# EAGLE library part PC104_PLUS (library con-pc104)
PC/104-Plus 16 bit
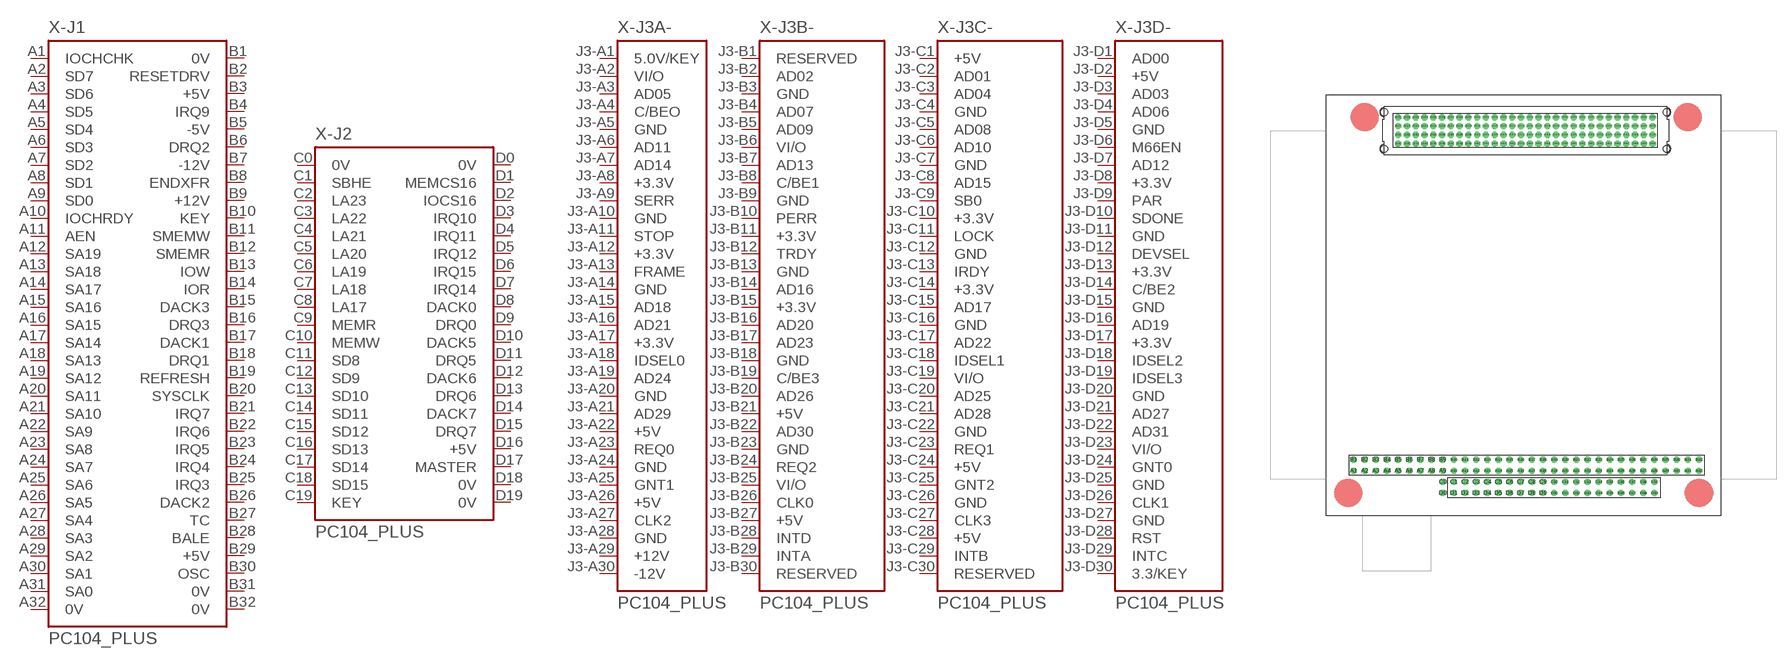
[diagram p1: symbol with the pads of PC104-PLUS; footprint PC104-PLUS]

Designator prefix X; gates -J1=PC104-J1 -J2=PC104-J2 -J3A-=PC104J3A -J3B-=PC104J3B -J3C-=PC104J3C -J3D-=PC104J3D

## PC104_PLUS  [PC104-PLUS]
A1  -J1:IOCHCHK  pas
A2  -J1:SD7  pas
A3  -J1:SD6  pas
A4  -J1:SD5  pas
A5  -J1:SD4  pas
A6  -J1:SD3  pas
A7  -J1:SD2  pas
A8  -J1:SD1  pas
A9  -J1:SD0  pas
A10  -J1:IOCHRDY  pas
A11  -J1:AEN  pas
A12  -J1:SA19  pas
A13  -J1:SA18  pas
A14  -J1:SA17  pas
A15  -J1:SA16  pas
A16  -J1:SA15  pas
A17  -J1:SA14  pas
A18  -J1:SA13  pas
A19  -J1:SA12  pas
A20  -J1:SA11  pas
A21  -J1:SA10  pas
A22  -J1:SA9  pas
A23  -J1:SA8  pas
A24  -J1:SA7  pas
A25  -J1:SA6  pas
A26  -J1:SA5  pas
A27  -J1:SA4  pas
A28  -J1:SA3  pas
A29  -J1:SA2  pas
A30  -J1:SA1  pas
A31  -J1:SA0  pas
A32  -J1:0V  pas
B1  -J1:0V  pas
B2  -J1:RESETDRV  pas
B3  -J1:+5V  pas
B4  -J1:IRQ9  pas
B5  -J1:-5V  pas
B6  -J1:DRQ2  pas
B7  -J1:-12V  pas
B8  -J1:ENDXFR  pas
B9  -J1:+12V  pas
B10  -J1:KEY  pas
B11  -J1:SMEMW  pas
B12  -J1:SMEMR  pas
B13  -J1:IOW  pas
B14  -J1:IOR  pas
B15  -J1:DACK3  pas
B16  -J1:DRQ3  pas
B17  -J1:DACK1  pas
B18  -J1:DRQ1  pas
B19  -J1:REFRESH  pas
B20  -J1:SYSCLK  pas
B21  -J1:IRQ7  pas
B22  -J1:IRQ6  pas
B23  -J1:IRQ5  pas
B24  -J1:IRQ4  pas
B25  -J1:IRQ3  pas
B26  -J1:DACK2  pas
B27  -J1:TC  pas
B28  -J1:BALE  pas
B29  -J1:+5V  pas
B30  -J1:OSC  pas
B31  -J1:0V  pas
B32  -J1:0V  pas
C0  -J2:0V  pas
C1  -J2:SBHE  pas
C2  -J2:LA23  pas
C3  -J2:LA22  pas
C4  -J2:LA21  pas
C5  -J2:LA20  pas
C6  -J2:LA19  pas
C7  -J2:LA18  pas
C8  -J2:LA17  pas
C9  -J2:MEMR  pas
C10  -J2:MEMW  pas
C11  -J2:SD8  pas
C12  -J2:SD9  pas
C13  -J2:SD10  pas
C14  -J2:SD11  pas
C15  -J2:SD12  pas
C16  -J2:SD13  pas
C17  -J2:SD14  pas
C18  -J2:SD15  pas
C19  -J2:KEY  pas
D0  -J2:0V  pas
D1  -J2:MEMCS16  pas
D2  -J2:IOCS16  pas
D3  -J2:IRQ10  pas
D4  -J2:IRQ11  pas
D5  -J2:IRQ12  pas
D6  -J2:IRQ15  pas
D7  -J2:IRQ14  pas
D8  -J2:DACK0  pas
D9  -J2:DRQ0  pas
D10  -J2:DACK5  pas
D11  -J2:DRQ5  pas
D12  -J2:DACK6  pas
D13  -J2:DRQ6  pas
D14  -J2:DACK7  pas
D15  -J2:DRQ7  pas
D16  -J2:+5V  pas
D17  -J2:MASTER  pas
D18  -J2:0V  pas
D19  -J2:0V  pas
J3-A1  -J3A-:5.0V/KEY  pas
J3-A2  -J3A-:VI/O  pas
J3-A3  -J3A-:AD05  pas
J3-A4  -J3A-:C/BEO  pas
J3-A5  -J3A-:GND  pas
J3-A6  -J3A-:AD11  pas
J3-A7  -J3A-:AD14  pas
J3-A8  -J3A-:+3.3V  pas
J3-A9  -J3A-:SERR  pas
J3-A10  -J3A-:GND  pas
J3-A11  -J3A-:STOP  pas
J3-A12  -J3A-:+3.3V  pas
J3-A13  -J3A-:FRAME  pas
J3-A14  -J3A-:GND  pas
J3-A15  -J3A-:AD18  pas
J3-A16  -J3A-:AD21  pas
J3-A17  -J3A-:+3.3V  pas
J3-A18  -J3A-:IDSEL0  pas
J3-A19  -J3A-:AD24  pas
J3-A20  -J3A-:GND  pas
J3-A21  -J3A-:AD29  pas
J3-A22  -J3A-:+5V  pas
J3-A23  -J3A-:REQ0  pas
J3-A24  -J3A-:GND  pas
J3-A25  -J3A-:GNT1  pas
J3-A26  -J3A-:+5V  pas
J3-A27  -J3A-:CLK2  pas
J3-A28  -J3A-:GND  pas
J3-A29  -J3A-:+12V  pas
J3-A30  -J3A-:-12V  pas
J3-B1  -J3B-:RESERVED  pas
J3-B2  -J3B-:AD02  pas
J3-B3  -J3B-:GND  pas
J3-B4  -J3B-:AD07  pas
J3-B5  -J3B-:AD09  pas
J3-B6  -J3B-:VI/O  pas
J3-B7  -J3B-:AD13  pas
J3-B8  -J3B-:C/BE1  pas
J3-B9  -J3B-:GND  pas
J3-B10  -J3B-:PERR  pas
J3-B11  -J3B-:+3.3V  pas
J3-B12  -J3B-:TRDY  pas
J3-B13  -J3B-:GND  pas
J3-B14  -J3B-:AD16  pas
J3-B15  -J3B-:+3.3V  pas
J3-B16  -J3B-:AD20  pas
J3-B17  -J3B-:AD23  pas
J3-B18  -J3B-:GND  pas
J3-B19  -J3B-:C/BE3  pas
J3-B20  -J3B-:AD26  pas
J3-B21  -J3B-:+5V  pas
J3-B22  -J3B-:AD30  pas
J3-B23  -J3B-:GND  pas
J3-B24  -J3B-:REQ2  pas
J3-B25  -J3B-:VI/O  pas
J3-B26  -J3B-:CLK0  pas
J3-B27  -J3B-:+5V  pas
J3-B28  -J3B-:INTD  pas
J3-B29  -J3B-:INTA  pas
J3-B30  -J3B-:RESERVED  pas
J3-C1  -J3C-:+5V  pas
J3-C2  -J3C-:AD01  pas
J3-C3  -J3C-:AD04  pas
J3-C4  -J3C-:GND  pas
J3-C5  -J3C-:AD08  pas
J3-C6  -J3C-:AD10  pas
J3-C7  -J3C-:GND  pas
J3-C8  -J3C-:AD15  pas
J3-C9  -J3C-:SB0  pas
J3-C10  -J3C-:+3.3V  pas
J3-C11  -J3C-:LOCK  pas
J3-C12  -J3C-:GND  pas
J3-C13  -J3C-:IRDY  pas
J3-C14  -J3C-:+3.3V  pas
J3-C15  -J3C-:AD17  pas
J3-C16  -J3C-:GND  pas
J3-C17  -J3C-:AD22  pas
J3-C18  -J3C-:IDSEL1  pas
J3-C19  -J3C-:VI/O  pas
J3-C20  -J3C-:AD25  pas
J3-C21  -J3C-:AD28  pas
J3-C22  -J3C-:GND  pas
J3-C23  -J3C-:REQ1  pas
J3-C24  -J3C-:+5V  pas
J3-C25  -J3C-:GNT2  pas
J3-C26  -J3C-:GND  pas
J3-C27  -J3C-:CLK3  pas
J3-C28  -J3C-:+5V  pas
J3-C29  -J3C-:INTB  pas
J3-C30  -J3C-:RESERVED  pas
J3-D1  -J3D-:AD00  pas
J3-D2  -J3D-:+5V  pas
J3-D3  -J3D-:AD03  pas
J3-D4  -J3D-:AD06  pas
J3-D5  -J3D-:GND  pas
J3-D6  -J3D-:M66EN  pas
J3-D7  -J3D-:AD12  pas
J3-D8  -J3D-:+3.3V  pas
J3-D9  -J3D-:PAR  pas
J3-D10  -J3D-:SDONE  pas
J3-D11  -J3D-:GND  pas
J3-D12  -J3D-:DEVSEL  pas
J3-D13  -J3D-:+3.3V  pas
J3-D14  -J3D-:C/BE2  pas
J3-D15  -J3D-:GND  pas
J3-D16  -J3D-:AD19  pas
J3-D17  -J3D-:+3.3V  pas
J3-D18  -J3D-:IDSEL2  pas
J3-D19  -J3D-:IDSEL3  pas
J3-D20  -J3D-:GND  pas
J3-D21  -J3D-:AD27  pas
J3-D22  -J3D-:AD31  pas
J3-D23  -J3D-:VI/O  pas
J3-D24  -J3D-:GNT0  pas
J3-D25  -J3D-:GND  pas
J3-D26  -J3D-:CLK1  pas
J3-D27  -J3D-:GND  pas
J3-D28  -J3D-:RST  pas
J3-D29  -J3D-:INTC  pas
J3-D30  -J3D-:3.3/KEY  pas

## Footprint PC104-PLUS (pad centres in mm)
PC/104-Plus 16 bit
drill 0.9 octagon: A1 6.35,10.16; A2 8.89,10.16; A3 11.43,10.16; A4 13.97,10.16; A5 16.51,10.16; A6 19.05,10.16; A7 21.59,10.16; A8 24.13,10.16; A9 26.67,10.16; A10 29.21,10.16; A11 31.75,10.16; A12 34.29,10.16; A13 36.83,10.16; A14 39.37,10.16; A15 41.91,10.16; A16 44.45,10.16; A17 46.99,10.16; A18 49.53,10.16; A19 52.07,10.16; A20 54.61,10.16; A21 57.15,10.16; A22 59.69,10.16; A23 62.23,10.16; A24 64.77,10.16; A25 67.31,10.16; A26 69.85,10.16; A27 72.39,10.16; A28 74.93,10.16; A29 77.47,10.16; A30 80.01,10.16; A31 82.55,10.16; A32 85.09,10.16; B1 6.35,12.7; B2 8.89,12.7; B3 11.43,12.7; B4 13.97,12.7; B5 16.51,12.7; B6 19.05,12.7; B7 21.59,12.7; B8 24.13,12.7; B9 26.67,12.7; B10 29.21,12.7; B11 31.75,12.7; B12 34.29,12.7; B13 36.83,12.7; B14 39.37,12.7; B15 41.91,12.7; B16 44.45,12.7; B17 46.99,12.7; B18 49.53,12.7; B19 52.07,12.7; B20 54.61,12.7; B21 57.15,12.7; B22 59.69,12.7; B23 62.23,12.7; B24 64.77,12.7; B25 67.31,12.7; B26 69.85,12.7; B27 72.39,12.7; B28 74.93,12.7; B29 77.47,12.7; B30 80.01,12.7; B31 82.55,12.7; B32 85.09,12.7; C0 26.67,7.62; C1 29.21,7.62; C2 31.75,7.62; C3 34.29,7.62; C4 36.83,7.62; C5 39.37,7.62; C6 41.91,7.62; C7 44.45,7.62; C8 46.99,7.62; C9 49.53,7.62; C10 52.07,7.62; C11 54.61,7.62; C12 57.15,7.62; C13 59.69,7.62; C14 62.23,7.62; C15 64.77,7.62; C16 67.31,7.62; C17 69.85,7.62; C18 72.39,7.62; C19 74.93,7.62; D0 26.67,5.08; D1 29.21,5.08; D2 31.75,5.08; D3 34.29,5.08; D4 36.83,5.08; D5 39.37,5.08; D6 41.91,5.08; D7 44.45,5.08; D8 46.99,5.08; D9 49.53,5.08; D10 52.07,5.08; D11 54.61,5.08; D12 57.15,5.08; D13 59.69,5.08; D14 62.23,5.08; D15 64.77,5.08; D16 67.31,5.08; D17 69.85,5.08; D18 72.39,5.08; D19 74.93,5.08; J3-A1 16.51,84.805; J3-A2 18.51,84.805; J3-A3 20.51,84.805; J3-A4 22.51,84.805; J3-A5 24.51,84.805; J3-A6 26.51,84.805; J3-A7 28.51,84.805; J3-A8 30.51,84.805; J3-A9 32.51,84.805; J3-A10 34.51,84.805; J3-A11 36.51,84.805; J3-A12 38.51,84.805; J3-A13 40.51,84.805; J3-A14 42.51,84.805; J3-A15 44.51,84.805; J3-A16 46.51,84.805; J3-A17 48.51,84.805; J3-A18 50.51,84.805; J3-A19 52.51,84.805; J3-A20 54.51,84.805; J3-A21 56.51,84.805; J3-A22 58.51,84.805; J3-A23 60.51,84.805; J3-A24 62.51,84.805; J3-A25 64.51,84.805; J3-A26 66.51,84.805; J3-A27 68.51,84.805; J3-A28 70.51,84.805; J3-A29 72.51,84.805; J3-A30 74.51,84.805; J3-B1 16.51,86.805; J3-B2 18.51,86.805; J3-B3 20.51,86.805; J3-B4 22.51,86.805; J3-B5 24.51,86.805; J3-B6 26.51,86.805; J3-B7 28.51,86.805; J3-B8 30.51,86.805; J3-B9 32.51,86.805; J3-B10 34.51,86.805; J3-B11 36.51,86.805; J3-B12 38.51,86.805; J3-B13 40.51,86.805; J3-B14 42.51,86.805; J3-B15 44.51,86.805; J3-B16 46.51,86.805; J3-B17 48.51,86.805; J3-B18 50.51,86.805; J3-B19 52.51,86.805; J3-B20 54.51,86.805; J3-B21 56.51,86.805; J3-B22 58.51,86.805; J3-B23 60.51,86.805; J3-B24 62.51,86.805; J3-B25 64.51,86.805; J3-B26 66.51,86.805; J3-B27 68.51,86.805; J3-B28 70.51,86.805; J3-B29 72.51,86.805; J3-B30 74.51,86.805; J3-C1 16.51,88.805; J3-C2 18.51,88.805; J3-C3 20.51,88.805; J3-C4 22.51,88.805; J3-C5 24.51,88.805; J3-C6 26.51,88.805; J3-C7 28.51,88.805; J3-C8 30.51,88.805; J3-C9 32.51,88.805; J3-C10 34.51,88.805; J3-C11 36.51,88.805; J3-C12 38.51,88.805; J3-C13 40.51,88.805; J3-C14 42.51,88.805; J3-C15 44.51,88.805; J3-C16 46.51,88.805; J3-C17 48.51,88.805; J3-C18 50.51,88.805; J3-C19 52.51,88.805; J3-C20 54.51,88.805; J3-C21 56.51,88.805; J3-C22 58.51,88.805; J3-C23 60.51,88.805; J3-C24 62.51,88.805; J3-C25 64.51,88.805; J3-C26 66.51,88.805; J3-C27 68.51,88.805; J3-C28 70.51,88.805; J3-C29 72.51,88.805; J3-C30 74.51,88.805; J3-D1 16.51,90.805; J3-D2 18.51,90.805; J3-D3 20.51,90.805; J3-D4 22.51,90.805; J3-D5 24.51,90.805; J3-D6 26.51,90.805; J3-D7 28.51,90.805; J3-D8 30.51,90.805; J3-D9 32.51,90.805; J3-D10 34.51,90.805; J3-D11 36.51,90.805; J3-D12 38.51,90.805; J3-D13 40.51,90.805; J3-D14 42.51,90.805; J3-D15 44.51,90.805; J3-D16 46.51,90.805; J3-D17 48.51,90.805; J3-D18 50.51,90.805; J3-D19 52.51,90.805; J3-D20 54.51,90.805; J3-D21 56.51,90.805; J3-D22 58.51,90.805; J3-D23 60.51,90.805; J3-D24 62.51,90.805; J3-D25 64.51,90.805; J3-D26 66.51,90.805; J3-D27 68.51,90.805; J3-D28 70.51,90.805; J3-D29 72.51,90.805; J3-D30 74.51,90.805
